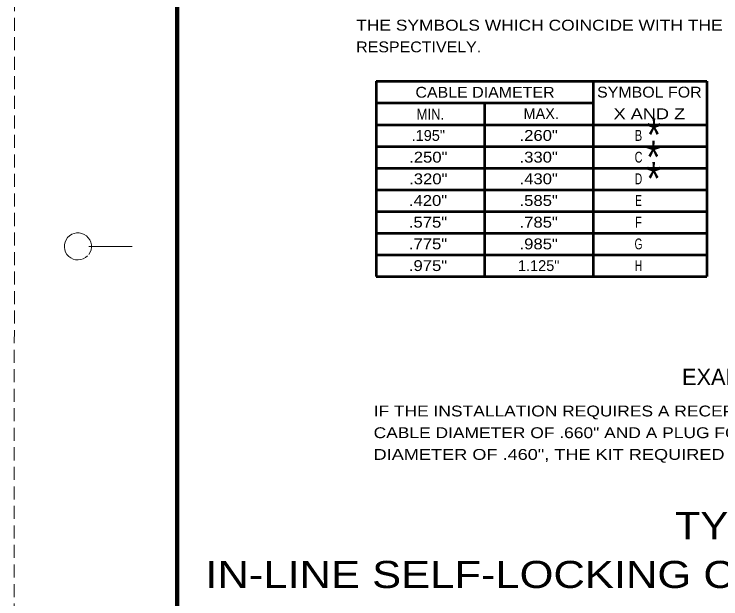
# Model space of a CAD drawing. Extents: x -1 to 679, y 0 to 440.
# Drawn here: x -1.3 to 129, y 221.2 to 329 of the extents above; entities that cross this region are included whole.
import ezdxf
from ezdxf.enums import TextEntityAlignment as Align

# ---------------------------------------------------------------- set-up
doc = ezdxf.new("R2010")
doc.units = 0
doc.header["$LTSCALE"] = 0.8
doc.linetypes.add('MEDIUM_DASHED', pattern=[4.5, 3, -1.5])
doc.layers.add('1', color=7, linetype='Continuous', lineweight=53)
doc.layers.add('61', color=7, linetype='Continuous', lineweight=35)

msp = doc.modelspace()

# ---------------------------------------------------------------- linework, layer by layer
at = {"layer": '1', "linetype": 'MEDIUM_DASHED', "lineweight": 13}
msp.add_line((-1.285, 439.9088), (-1.345, -0.1312), dxfattribs=at)
at = {"layer": '1'}
for p, q in [((65.4295, 316.5926), (126.4295, 316.5926)), ((65.4295, 316.5926), (65.4295, 280.5926)), ((105.4295, 316.5926), (105.4295, 280.5926)), ((126.4295, 316.5926), (126.4295, 280.5926)), ((65.4295, 312.5926), (105.4295, 312.5926)), ((85.4295, 312.5926), (85.4295, 280.5926)), ((65.4295, 308.5926), (126.4295, 308.5926)), ((65.4295, 304.5926), (126.4295, 304.5926)), ((65.4295, 300.5926), (126.4295, 300.5926)), ((65.4295, 296.5926), (126.4295, 296.5926)), ((65.4295, 292.5926), (126.4295, 292.5926)), ((65.4295, 288.5926), (126.4295, 288.5926)), ((65.4295, 284.5926), (126.4295, 284.5926)), ((65.4295, 280.5926), (126.4295, 280.5926))]:
    msp.add_line(p, q, dxfattribs=at)
at = {"layer": '61', "lineweight": 13}
msp.add_line((12.415, 286.1488), (20.415, 286.1488), dxfattribs=at)
at = {"layer": '61', "lineweight": 158}
msp.add_lwpolyline([(667.755, 429.9088), (28.715, 429.9088), (28.715, 9.8888)], dxfattribs=at)
at = {"layer": '61', "lineweight": 13}
msp.add_arc((10.4128, 286.1501), 2.5, 323.13009, 315.37577, dxfattribs=at)

# ---------------------------------------------------------------- texts
at = {"layer": '1'}
for s, height, width, p in [('THE SYMBOLS WHICH COINCIDE WITH THE REQUIREMENTS AND SUBSTITUTE FOR (W,X) (Y,Z)', 2, 1.2, (61.7367, 325.93)), ('RESPECTIVELY.', 2, 1.1, (61.7367, 321.93)), ('CABLE DIAMETER', 2, 1.1, (72.6655, 313.5662)), ('MIN.', 2, 0.9, (72.8815, 309.5151)), ('*', 6, 0.85, (115.3231, 303.7357)), ('*', 6, 0.85, (115.2151, 299.6305)), ('*', 6, 0.85, (115.2691, 295.6874)), ('IF THE INSTALLATION REQUIRES A RECEPTACLE FOR NO. 6 STRANDED CONDUCTOR AND A', 2, 1.2, (64.9528, 254.8007)), ('CABLE DIAMETER OF .660" AND A PLUG FOR NO. 8 SOLID CONDUCTOR AND A CABLE', 2, 1.2, (64.9528, 250.8007)), ('DIAMETER OF .460", THE KIT REQUIRED WILL BE I-F3-E6.', 2, 1.25, (64.9528, 246.8007))]:
    msp.add_text(s, height=height, dxfattribs=dict(at, width=width)).set_placement(p)
for s, height, width, p in [('SYMBOL FOR', 2, 1.1, (115.8091, 313.5939)), ('X AND Z', 2, 1.25, (115.8091, 309.5939)), ('.260"', 2, 1.15, (95.3982, 305.6071)), ('B', 2, 0.75, (113.8111, 305.6071)), ('.250"', 2, 1.15, (75.0414, 301.6012)), ('.330"', 2, 1.15, (95.3982, 301.6071)), ('C', 2, 0.75, (113.811, 301.6071)), ('.320"', 2, 1.15, (75.0414, 297.6012)), ('.430"', 2, 1.15, (95.3982, 297.6071)), ('D', 2, 0.7, (113.8111, 297.6071)), ('.420"', 2, 1.15, (74.9874, 293.6115)), ('.585"', 2, 1.15, (95.3982, 293.6071)), ('E', 2, 0.7, (113.8111, 293.6071)), ('.575"', 2, 1.15, (74.9874, 289.6115)), ('.785"', 2, 1.15, (95.3982, 289.6071)), ('F', 2, 0.75, (113.8111, 289.6071)), ('.775"', 2, 1.15, (74.9874, 285.6115)), ('.985"', 2, 1.15, (95.3982, 285.6071)), ('G', 2, 0.7, (113.811, 285.6071)), ('.975"', 2, 1.15, (74.9874, 281.6115)), ('H', 2, 0.7, (113.8111, 281.6071)), ('TYPE 1', 5, 1.15, (133.7752, 232.1718)), ('IN-LINE SELF-LOCKING CONNECTOR KIT FOR PULL', 5, 1.2, (133.7752, 223.1718))]:
    msp.add_text(s, height=height, dxfattribs=dict(at, width=width)).set_placement(p, align=Align.CENTER)
for s, height, p in [('MAX.', 2, (92.5904, 309.6231)), ('EXAMPLE', 3, (121.8305, 260.5921))]:
    msp.add_text(s, height=height, dxfattribs=at).set_placement(p)
for s, p in [('.195"', (75.0415, 305.6012)), ('1.125"', (95.3983, 281.6071))]:
    msp.add_text(s, height=2, dxfattribs=at).set_placement(p, align=Align.CENTER)

doc.saveas('drawing.dxf')
